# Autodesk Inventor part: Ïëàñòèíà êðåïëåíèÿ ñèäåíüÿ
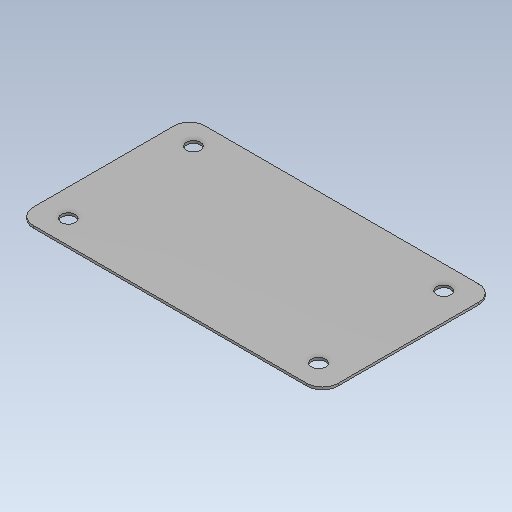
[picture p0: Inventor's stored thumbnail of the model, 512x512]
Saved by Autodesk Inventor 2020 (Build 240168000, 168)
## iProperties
Created: 1900-01
Part Number: Ïëàñòèíà êðåïëåíèÿ ñèäåíüÿ
Material: Générique
Document SubType Name: Modeling
Designer: bruno
Density: 1 g/cm^3
Appearance: Par défaut
Author: bruno
Revision Number: ANYUNSPECIFIED
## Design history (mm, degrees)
feature "Base1"
node "Solide1"
